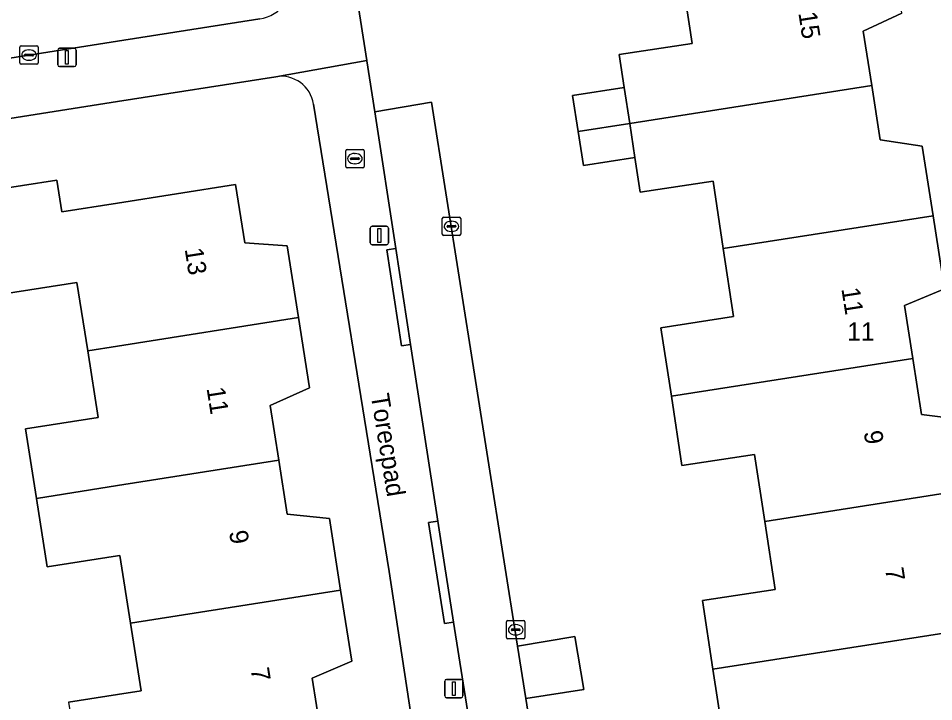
# Model space of a CAD drawing. Extents: x 160077 to 160948, y 386481 to 387498.
# Drawn here: x 160494.61 to 160544.36, y 387171.58 to 387208.7 of the extents above; entities that cross this region are included whole.
import ezdxf

# ---------------------------------------------------------------- set-up
doc = ezdxf.new("R2010")
doc.units = 0
for name, color, linetype in [('IMGEO_Brandkraan', 7, 'Continuous'), ('IMGEO_Erf', 7, 'Continuous'), ('IMGEO_Groenvoorziening', 7, 'Continuous'), ('IMGEO_Kolk', 7, 'Continuous'), ('IMGEO_Lichtmast', 7, 'Continuous'), ('IMGEO_Openbare_ruimte_label', 7, 'Continuous'), ('IMGEO_Pand', 7, 'Continuous'), ('IMGEO_Pand_nummerreeks', 7, 'Continuous'), ('IMGEO_Rijbaan_lokaal_open', 7, 'Continuous'), ('IMGEO_Voetpad_open', 7, 'Continuous')]:
    doc.layers.add(name, color=color, linetype=linetype)

msp = doc.modelspace()

# ---------------------------------------------------------------- linework, layer by layer
at = {"layer": 'IMGEO_Brandkraan'}
for p, q in [((160512.397, 387200.653), (160512.397, 387201.505)), ((160512.472, 387201.579), (160513.324, 387201.579)), ((160512.885, 387201.359), (160512.91, 387201.359)), ((160513.398, 387201.505), (160513.398, 387200.653)), ((160512.656, 387201.073), (160512.656, 387201.085)), ((160513.094, 387201.036), (160512.696, 387201.036)), ((160512.699, 387201.122), (160513.097, 387201.122)), ((160512.908, 387200.799), (160512.883, 387200.799)), ((160513.14, 387201.085), (160513.14, 387201.073)), ((160513.324, 387200.579), (160512.472, 387200.579))]:
    msp.add_line(p, q, dxfattribs=at)
for points in [[(160512.397, 387200.653), (160512.397, 387201.505)], [(160512.472, 387201.579), (160513.324, 387201.579)], [(160513.398, 387201.505), (160513.398, 387200.653)], [(160513.324, 387200.579), (160512.472, 387200.579)]]:
    msp.add_lwpolyline(points, dxfattribs=at)
for centre, radius, start, end in [((160512.474, 387201.503), 0.0765, 91.552, 178.448), ((160512.474, 387201.503), 0.0765, 91.552, 178.448), ((160513.322, 387201.503), 0.0765, 1.552, 88.448), ((160513.322, 387201.503), 0.0765, 1.552, 88.448), ((160512.696, 387201.082), 0.0403, 85.8775, 175.7526), ((160512.693, 387201.072), 0.0366, 178.938, 274.7102), ((160513.097, 387201.079), 0.043, 264.8664, 352.4533), ((160513.101, 387201.084), 0.0386, 1.7309, 96.639), ((160512.474, 387200.655), 0.0765, 181.552, 268.448), ((160512.474, 387200.655), 0.0765, 181.552, 268.448), ((160513.322, 387200.655), 0.0765, 271.552, 358.448), ((160513.322, 387200.655), 0.0765, 271.552, 358.448)]:
    msp.add_arc(centre, radius, start, end, dxfattribs=at)
for centre, major_axis, ratio, start_param, end_param in [((160512.884, 387201.079), (-0.387, 0.002), 0.722429, 4.712389, 7.853982), ((160512.909, 387201.079), (-0.39, 0.002), 0.717154, 1.570796, 4.712389)]:
    msp.add_ellipse(centre, major_axis=major_axis, ratio=ratio, start_param=start_param, end_param=end_param, dxfattribs=at)
at = {"layer": 'IMGEO_Erf'}
for points in [[(160508.282, 387239.959), (160513.55, 387206.404), (160513.553, 387206.385), (160513.988, 387203.613), (160517.066, 387204.154), (160521.734, 387174.596), (160524.845, 387175.123), (160525.334, 387172.241), (160522.184, 387171.749), (160522.731, 387168.284)], [(160532.929, 387169.592), (160532.358, 387173.34), (160531.79, 387177.065), (160535.745, 387177.668), (160535.181, 387181.37), (160534.625, 387185.013), (160530.67, 387184.41), (160530.097, 387188.166), (160529.529, 387191.894), (160533.484, 387192.497), (160532.92, 387196.197), (160532.362, 387199.852), (160528.407, 387199.249), (160528.117, 387201.149), (160525.315, 387200.711), (160525.027, 387202.553), (160524.722, 387204.504), (160527.538, 387204.945), (160527.266, 387206.732), (160531.221, 387207.335), (160530.659, 387211.023)], [(160542.63, 387208.977), (160540.529, 387208.007), (160540.992, 387205.05), (160541.453, 387202.101), (160543.732, 387201.748), (160544.321, 387197.98), (160544.944, 387194), (160542.767, 387193.103), (160543.218, 387190.217), (160543.692, 387187.187), (160546.01, 387186.893)], [(160508.597, 387205.531), (160500, 387204.183), (160486.443, 387202.053)], [(160519.378, 387148.285), (160514.764, 387178.646), (160510.656, 387204.038)], [(160492.957, 387199.323), (160496.699, 387199.913), (160496.971, 387198.184), (160500, 387198.661), (160506.414, 387199.672), (160506.913, 387196.508), (160509.219, 387196.349), (160509.834, 387192.446), (160510.436, 387188.629), (160508.296, 387187.663), (160508.764, 387184.695), (160509.225, 387181.771), (160511.51, 387181.522), (160512.122, 387177.642), (160512.731, 387173.778), (160510.578, 387172.854), (160511.045, 387169.889)], [(160497.336, 387171.545), (160500, 387171.966), (160501.287, 387172.168), (160500.707, 387175.846), (160500.127, 387179.527), (160500, 387179.507), (160496.176, 387178.904), (160495.589, 387182.623), (160494.995, 387186.391), (160498.947, 387187.014), (160498.375, 387190.643), (160497.79, 387194.354), (160493.838, 387193.731)]]:
    msp.add_lwpolyline(points, dxfattribs=at)
msp.add_arc((160508.878, 387203.752), 1.801, 9.144, 98.9636, dxfattribs=at)
at = {"layer": 'IMGEO_Groenvoorziening'}
msp.add_lwpolyline([(160451.075, 387199.755), (160500, 387207.46), (160507.733, 387208.672)], dxfattribs=at)
msp.add_arc((160507.405, 387210.779), 2.132, 278.8612, 8.9109, dxfattribs=at)
at = {"layer": 'IMGEO_Kolk'}
for p, q in [((160494.763, 387207.205), (160495.615, 387207.205)), ((160494.688, 387206.279), (160494.688, 387207.131)), ((160494.947, 387206.699), (160494.947, 387206.711)), ((160494.99, 387206.748), (160495.388, 387206.748)), ((160495.176, 387206.985), (160495.201, 387206.985)), ((160495.431, 387206.711), (160495.431, 387206.699)), ((160495.689, 387207.131), (160495.689, 387206.279)), ((160495.615, 387206.205), (160494.763, 387206.205)), ((160495.385, 387206.662), (160494.987, 387206.662)), ((160495.199, 387206.425), (160495.174, 387206.425)), ((160517.646, 387196.975), (160517.646, 387197.827)), ((160517.721, 387197.901), (160518.573, 387197.901)), ((160518.647, 387197.827), (160518.647, 387196.975)), ((160517.905, 387197.395), (160517.905, 387197.407)), ((160518.343, 387197.358), (160517.945, 387197.358)), ((160517.948, 387197.444), (160518.346, 387197.444)), ((160518.134, 387197.681), (160518.159, 387197.681)), ((160518.389, 387197.407), (160518.389, 387197.395)), ((160518.573, 387196.901), (160517.721, 387196.901)), ((160518.157, 387197.121), (160518.132, 387197.121)), ((160521.14, 387175.057), (160521.14, 387175.909)), ((160521.215, 387175.983), (160522.067, 387175.983)), ((160522.141, 387175.909), (160522.141, 387175.057)), ((160521.399, 387175.477), (160521.399, 387175.489)), ((160521.837, 387175.44), (160521.439, 387175.44)), ((160521.442, 387175.526), (160521.84, 387175.526)), ((160521.628, 387175.763), (160521.653, 387175.763)), ((160521.883, 387175.489), (160521.883, 387175.477)), ((160522.067, 387174.983), (160521.215, 387174.983)), ((160521.651, 387175.203), (160521.626, 387175.203))]:
    msp.add_line(p, q, dxfattribs=at)
for points in [[(160494.763, 387207.205), (160495.615, 387207.205)], [(160494.688, 387206.279), (160494.688, 387207.131)], [(160495.689, 387207.131), (160495.689, 387206.279)], [(160495.615, 387206.205), (160494.763, 387206.205)], [(160517.646, 387196.975), (160517.646, 387197.827)], [(160517.721, 387197.901), (160518.573, 387197.901)], [(160518.647, 387197.827), (160518.647, 387196.975)], [(160518.573, 387196.901), (160517.721, 387196.901)], [(160521.14, 387175.057), (160521.14, 387175.909)], [(160521.215, 387175.983), (160522.067, 387175.983)], [(160522.141, 387175.909), (160522.141, 387175.057)], [(160522.067, 387174.983), (160521.215, 387174.983)]]:
    msp.add_lwpolyline(points, dxfattribs=at)
for centre, radius, start, end in [((160494.765, 387207.129), 0.0765, 91.552, 178.448), ((160494.765, 387207.129), 0.0765, 91.552, 178.448), ((160495.613, 387207.129), 0.0765, 1.552, 88.448), ((160495.613, 387207.129), 0.0765, 1.552, 88.448), ((160494.987, 387206.708), 0.0403, 85.8775, 175.7526), ((160494.984, 387206.698), 0.0366, 178.938, 274.7102), ((160495.388, 387206.705), 0.043, 264.8664, 352.4533), ((160495.392, 387206.71), 0.0386, 1.7309, 96.639), ((160494.765, 387206.281), 0.0765, 181.552, 268.448), ((160494.765, 387206.281), 0.0765, 181.552, 268.448), ((160495.613, 387206.281), 0.0765, 271.552, 358.448), ((160495.613, 387206.281), 0.0765, 271.552, 358.448), ((160517.723, 387197.825), 0.0765, 91.552, 178.448), ((160517.723, 387197.825), 0.0765, 91.552, 178.448), ((160518.571, 387197.825), 0.0765, 1.552, 88.448), ((160518.571, 387197.825), 0.0765, 1.552, 88.448), ((160517.945, 387197.404), 0.0403, 85.8775, 175.7526), ((160517.942, 387197.394), 0.0366, 178.938, 274.7102), ((160518.346, 387197.401), 0.043, 264.8664, 352.4533), ((160518.35, 387197.406), 0.0386, 1.7309, 96.639), ((160517.723, 387196.977), 0.0765, 181.552, 268.448), ((160517.723, 387196.977), 0.0765, 181.552, 268.448), ((160518.571, 387196.977), 0.0765, 271.552, 358.448), ((160518.571, 387196.977), 0.0765, 271.552, 358.448), ((160521.217, 387175.907), 0.0765, 91.552, 178.448), ((160521.217, 387175.907), 0.0765, 91.552, 178.448), ((160522.065, 387175.907), 0.0765, 1.552, 88.448), ((160522.065, 387175.907), 0.0765, 1.552, 88.448), ((160521.439, 387175.486), 0.0403, 85.8775, 175.7526), ((160521.436, 387175.476), 0.0366, 178.938, 274.7102), ((160521.84, 387175.483), 0.043, 264.8664, 352.4533), ((160521.844, 387175.488), 0.0386, 1.7309, 96.639), ((160521.217, 387175.059), 0.0765, 181.552, 268.448), ((160521.217, 387175.059), 0.0765, 181.552, 268.448), ((160522.065, 387175.059), 0.0765, 271.552, 358.448), ((160522.065, 387175.059), 0.0765, 271.552, 358.448)]:
    msp.add_arc(centre, radius, start, end, dxfattribs=at)
for centre, major_axis, ratio, start_param, end_param in [((160495.175, 387206.705), (-0.387, 0.002), 0.722429, 4.712389, 7.853982), ((160495.2, 387206.705), (-0.39, 0.002), 0.717154, 1.570796, 4.712389), ((160518.133, 387197.401), (-0.387, 0.002), 0.722429, 4.712389, 7.853982), ((160518.158, 387197.401), (-0.39, 0.002), 0.717154, 1.570796, 4.712389), ((160521.627, 387175.483), (-0.387, 0.002), 0.722429, 4.712389, 7.853982), ((160521.652, 387175.483), (-0.39, 0.002), 0.717154, 1.570796, 4.712389)]:
    msp.add_ellipse(centre, major_axis=major_axis, ratio=ratio, start_param=start_param, end_param=end_param, dxfattribs=at)
at = {"layer": 'IMGEO_Lichtmast'}
for p, q in [((160496.751, 387206.179), (160496.751, 387206.979)), ((160496.751, 387206.979), (160496.751, 387206.179)), ((160496.851, 387207.079), (160497.641, 387207.079)), ((160497.641, 387207.079), (160496.851, 387207.079)), ((160497.741, 387206.979), (160497.741, 387206.179)), ((160497.741, 387206.179), (160497.741, 387206.979)), ((160497.641, 387206.079), (160496.851, 387206.079)), ((160496.851, 387206.079), (160497.641, 387206.079)), ((160513.732, 387196.504), (160513.732, 387197.304)), ((160513.732, 387197.304), (160513.732, 387196.504)), ((160513.832, 387197.404), (160514.622, 387197.404)), ((160514.622, 387197.404), (160513.832, 387197.404)), ((160514.722, 387197.304), (160514.722, 387196.504)), ((160514.722, 387196.504), (160514.722, 387197.304)), ((160514.622, 387196.404), (160513.832, 387196.404)), ((160513.832, 387196.404), (160514.622, 387196.404)), ((160517.778, 387171.888), (160517.778, 387172.688)), ((160517.778, 387172.688), (160517.778, 387171.888)), ((160517.878, 387172.788), (160518.668, 387172.788)), ((160518.668, 387172.788), (160517.878, 387172.788)), ((160518.768, 387172.688), (160518.768, 387171.888)), ((160518.768, 387171.888), (160518.768, 387172.688)), ((160518.668, 387171.788), (160517.878, 387171.788)), ((160517.878, 387171.788), (160518.668, 387171.788))]:
    msp.add_line(p, q, dxfattribs=at)
for points in [[(160497.171, 387206.954), (160497.321, 387206.954), (160497.321, 387206.204), (160497.171, 387206.204), (160497.171, 387206.954)], [(160514.152, 387197.279), (160514.302, 387197.279), (160514.302, 387196.529), (160514.152, 387196.529), (160514.152, 387197.279)], [(160518.198, 387172.663), (160518.348, 387172.663), (160518.348, 387171.913), (160518.198, 387171.913), (160518.198, 387172.663)]]:
    msp.add_lwpolyline(points, dxfattribs=at)
for centre, start, end in [((160496.851, 387206.979), 90, 180), ((160496.851, 387206.979), 90, 180), ((160497.641, 387206.979), 0, 90), ((160497.641, 387206.979), 360, 90), ((160496.851, 387206.179), 180, 270), ((160496.851, 387206.179), 180, 270), ((160497.641, 387206.179), 270, 0), ((160497.641, 387206.179), 270, 0), ((160513.832, 387197.304), 90, 180), ((160513.832, 387197.304), 90, 180), ((160514.622, 387197.304), 0, 90), ((160514.622, 387197.304), 360, 90), ((160513.832, 387196.504), 180, 270), ((160513.832, 387196.504), 180, 270), ((160514.622, 387196.504), 270, 0), ((160514.622, 387196.504), 270, 0), ((160517.878, 387172.688), 90, 180), ((160517.878, 387172.688), 90, 180), ((160518.668, 387172.688), 0, 90), ((160518.668, 387172.688), 360, 90), ((160517.878, 387171.888), 180, 270), ((160517.878, 387171.888), 180, 270), ((160518.668, 387171.888), 270, 0), ((160518.668, 387171.888), 270, 0)]:
    msp.add_arc(centre, 0.1, start, end, dxfattribs=at)
at = {"layer": 'IMGEO_Pand'}
for points in [[(160540.529, 387208.007), (160542.63, 387208.977), (160542.032, 387212.801), (160530.659, 387211.023), (160531.221, 387207.335), (160527.266, 387206.732), (160527.538, 387204.945), (160527.836, 387202.992), (160540.992, 387205.05)], [(160527.538, 387204.945), (160524.722, 387204.504), (160525.027, 387202.553), (160527.836, 387202.992)], [(160543.732, 387201.748), (160541.453, 387202.101), (160540.992, 387205.05), (160527.836, 387202.992), (160528.117, 387201.149), (160528.407, 387199.249), (160532.362, 387199.852), (160532.92, 387196.197), (160544.321, 387197.98)], [(160527.836, 387202.992), (160525.027, 387202.553), (160525.315, 387200.711), (160528.117, 387201.149)], [(160509.834, 387192.446), (160509.219, 387196.349), (160506.913, 387196.508), (160506.414, 387199.672), (160500, 387198.661), (160496.971, 387198.184), (160496.699, 387199.913), (160492.957, 387199.323), (160493.838, 387193.731), (160497.79, 387194.354), (160498.375, 387190.643), (160500, 387190.899)], [(160543.218, 387190.217), (160542.767, 387193.103), (160544.944, 387194), (160544.321, 387197.98), (160532.92, 387196.197), (160533.484, 387192.497), (160529.529, 387191.894), (160530.097, 387188.166)], [(160500, 387190.899), (160498.375, 387190.643), (160498.947, 387187.014), (160494.995, 387186.391), (160495.589, 387182.623), (160500, 387183.317), (160508.764, 387184.695), (160508.296, 387187.663), (160510.436, 387188.629), (160509.834, 387192.446)], [(160530.097, 387188.166), (160530.67, 387184.41), (160534.625, 387185.013), (160535.181, 387181.37), (160546.594, 387183.155), (160546.01, 387186.893), (160543.692, 387187.187), (160543.218, 387190.217)], [(160500, 387183.317), (160495.589, 387182.623), (160496.176, 387178.904), (160500, 387179.507), (160500.127, 387179.527), (160500.707, 387175.846), (160512.122, 387177.642), (160511.51, 387181.522), (160509.225, 387181.771), (160508.764, 387184.695)], [(160545.492, 387175.394), (160545.038, 387178.3), (160547.212, 387179.204), (160546.594, 387183.155), (160535.181, 387181.37), (160535.745, 387177.668), (160531.79, 387177.065), (160532.358, 387173.34)], [(160511.045, 387169.889), (160510.578, 387172.854), (160512.731, 387173.778), (160512.122, 387177.642), (160500.707, 387175.846), (160501.287, 387172.168), (160500, 387171.966), (160497.336, 387171.545), (160497.922, 387167.825), (160500, 387168.152)], [(160548.402, 387172.097), (160545.968, 387172.349), (160545.492, 387175.394), (160532.358, 387173.34), (160532.929, 387169.592), (160534.361, 387169.81), (160534.916, 387166.149), (160537.44, 387166.544), (160548.988, 387168.35)], [(160522.184, 387171.749), (160525.334, 387172.241), (160524.845, 387175.123), (160521.734, 387174.596)]]:
    msp.add_lwpolyline(points, close=True, dxfattribs=at)
at = {"layer": 'IMGEO_Rijbaan_lokaal_open'}
msp.add_lwpolyline([(160525.778, 387149.084), (160525.725, 387149.326), (160522.731, 387168.284), (160522.184, 387171.749), (160521.734, 387174.596), (160517.066, 387204.154), (160513.988, 387203.613), (160515.125, 387196.205), (160515.927, 387190.987), (160517.401, 387181.386), (160517.762, 387179.037), (160518.256, 387175.902), (160519.716, 387166.643), (160520.588, 387161.109), (160522.053, 387151.816), (160522.517, 387148.875), (160522.567, 387148.56)], close=True, dxfattribs=at)
at = {"layer": 'IMGEO_Voetpad_open'}
for points in [[(160485.133, 387201.848), (160486.443, 387202.053), (160500, 387204.183), (160508.597, 387205.531), (160513.55, 387206.404), (160508.282, 387239.959), (160502.892, 387236.932), (160502.873, 387236.9)], [(160507.733, 387208.672), (160500, 387207.46), (160451.075, 387199.755)], [(160514.631, 387196.13), (160515.125, 387196.205), (160513.988, 387203.613), (160513.553, 387206.385), (160513.55, 387206.404), (160508.597, 387205.531)], [(160510.656, 387204.038), (160514.764, 387178.646), (160519.378, 387148.285), (160522.023, 387148.799), (160521.559, 387151.74), (160522.053, 387151.816), (160520.588, 387161.109), (160520.095, 387161.032), (160519.223, 387166.566), (160519.716, 387166.643), (160518.256, 387175.902), (160517.762, 387175.827), (160516.907, 387181.311), (160517.401, 387181.386), (160515.927, 387190.987), (160515.433, 387190.912), (160514.631, 387196.13)]]:
    msp.add_lwpolyline(points, dxfattribs=at)
for points in [[(160515.927, 387190.987), (160515.125, 387196.205), (160514.631, 387196.13), (160515.433, 387190.912)], [(160517.401, 387181.386), (160516.907, 387181.311), (160517.762, 387175.827), (160518.256, 387175.902), (160517.762, 387179.037)]]:
    msp.add_lwpolyline(points, close=True, dxfattribs=at)
for centre, radius, start, end in [((160507.405, 387210.779), 2.132, 278.8612, 8.9109), ((160508.878, 387203.752), 1.801, 9.144, 98.9636)]:
    msp.add_arc(centre, radius, start, end, dxfattribs=at)

# ---------------------------------------------------------------- texts
at = {"layer": 'IMGEO_Openbare_ruimte_label'}
msp.add_text('Torecpad', height=1, rotation=279.208, dxfattribs=at).set_placement((160513.756, 387188.235))
at = {"layer": 'IMGEO_Pand_nummerreeks'}
for s, rotation, p in [('15', 278.8692, (160536.998, 387208.994)), ('13', 278.9353, (160503.645, 387196.165)), ('11', 278.8684, (160539.336, 387194.011)), ('11', 278.9353, (160504.834, 387188.602)), ('9', 278.8684, (160540.55, 387186.233)), ('9', 278.9353, (160506.058, 387180.811)), ('7', 278.8684, (160541.71, 387178.797)), ('7', 278.9353, (160507.23, 387173.361))]:
    msp.add_text(s, height=1, rotation=rotation, dxfattribs=at).set_placement(p)
msp.add_text('11', height=1, dxfattribs=at).set_placement((160539.654, 387191.182))

doc.saveas('drawing.dxf')
